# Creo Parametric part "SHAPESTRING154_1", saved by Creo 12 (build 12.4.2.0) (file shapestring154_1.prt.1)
Units: Custom; MM, KILOGRAM, SECS

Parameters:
  PTC_WM_ITERATION = "0"
  PTC_WM_VERSION = "-.0"
  PTC_WM_LIFECYCLE_STATE = "In Work"
  PTC_WM_LIFECYCLE = "MO_CADDocument"
  PTC_WM_CREATED_BY = "Maximilian Roepper (Z0017RMS: MO)"
  PTC_WM_CREATED_ON = "18-Sep-26 11:36:42 AM"
  PTC_WM_MODIFIED_BY = "Maximilian Roepper (Z0017RMS: MO)"
  PTC_WM_MODIFIED_ON = "18-Sep-26 11:36:46 AM"
  PDMLINKNUMBER = "PDM000071454795"
  PTC_WM_NAME = "shapestring154_1.prt"
  PTC_WM_NUMBER = "PDM000071454795"

Other parameters: WEIGHT, WEIGHT_FACTOR, WEIGHT_ADD, _MASS_TEMP, _DIFF_TEMP, MC_ERRORS, SUPPLIER

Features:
  1. coordinate system
  2. datum plane "PRT_YZ"
  3. datum plane "PRT_XY"
  4. datum plane "PRT_XZ"
  5. coordinate system
  6. datum axis
  7. datum axis
  8. datum axis
  9. coordinate system
  10. imported feature

Other named items: PRT, SIEMENS_MO, DRW_VIEW_ORG, PRT_X, PRT_Y, PRT_Z, CS0, ROUGH_GROB

Layers: 00_STD_CSYS-KSYS, 01_STD_PLANES-EBENEN, 02_STD_AXES-ACHSEN, 03_STD_CSYS-KSYS, 24_IMPORT_FEAT-IMPORT_KE, INTFCLR

Surfaces: 1 plane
